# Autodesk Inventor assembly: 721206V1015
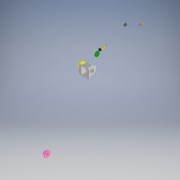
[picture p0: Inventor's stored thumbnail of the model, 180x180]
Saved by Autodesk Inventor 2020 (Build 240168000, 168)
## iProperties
Created: 2022-12
Part Number: 721206V1015
Document SubType Name: Assembly
Designer: com
Author: com
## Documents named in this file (15)
- C:\Users\com\Desktop\721206V1015\721206V1015.iam
- C:\Users\com\Desktop\부품1.ipt
- C:\Users\com\Desktop\721206V1015\V-벨트풀리.ipt
- C:\Users\com\Desktop\721206V1015\뒤커버.ipt
- C:\Users\com\Desktop\721206V1015\멈춤나사 - M4x10.ipt
- C:\Users\com\Desktop\721206V1015\베어링 6203.ipt
- C:\Users\com\Desktop\721206V1015\볼트 M3 x 8.ipt
- C:\Users\com\Desktop\721206V1015\볼트 M3 x 10.ipt
- C:\Users\com\Desktop\721206V1015\스퍼기어.ipt
- C:\Users\com\Desktop\721206V1015\앞커버.ipt
- C:\Users\com\Desktop\721206V1015\오일 실 17 x 32 x 8.ipt
- C:\Users\com\Desktop\721206V1015\축.ipt
- C:\Users\com\Desktop\721206V1015\칼라.ipt
- C:\Users\com\Desktop\721206V1015\키 - 5 x 5 x 18.ipt
- C:\Users\com\Desktop\721206V1015\키 - 6 x 6 x 22.ipt
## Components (3 placed, 3 different names)
1. V-벨트풀리:1
2. ISO 4762 M3 x 8:1
3. ISO 4762 M3 x 10:1
